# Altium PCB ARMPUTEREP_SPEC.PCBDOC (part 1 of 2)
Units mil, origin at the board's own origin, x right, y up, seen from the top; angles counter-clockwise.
Board outline 6000 x 4000 mil, 2 copper layers (Top Layer, Bottom Layer); 67 components, 140 nets, 541 pads, 398 vias.
Unrouted connection lines stored in the file: 6.
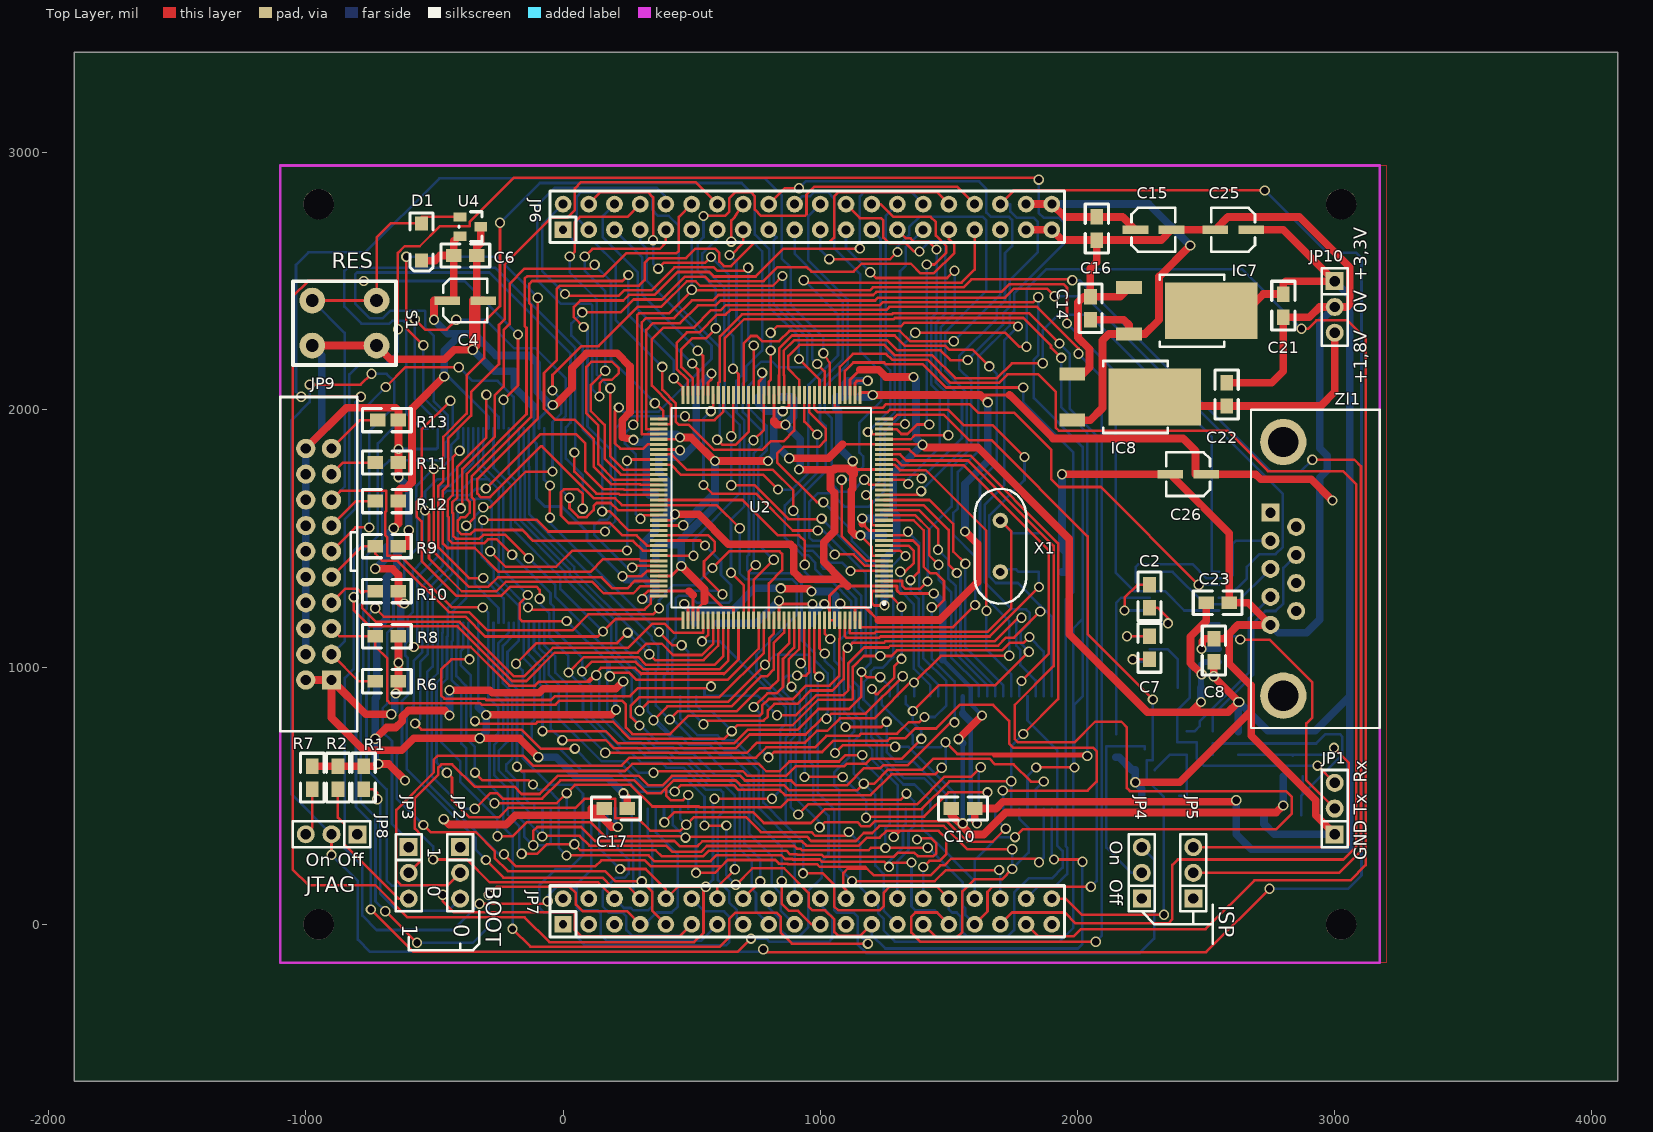
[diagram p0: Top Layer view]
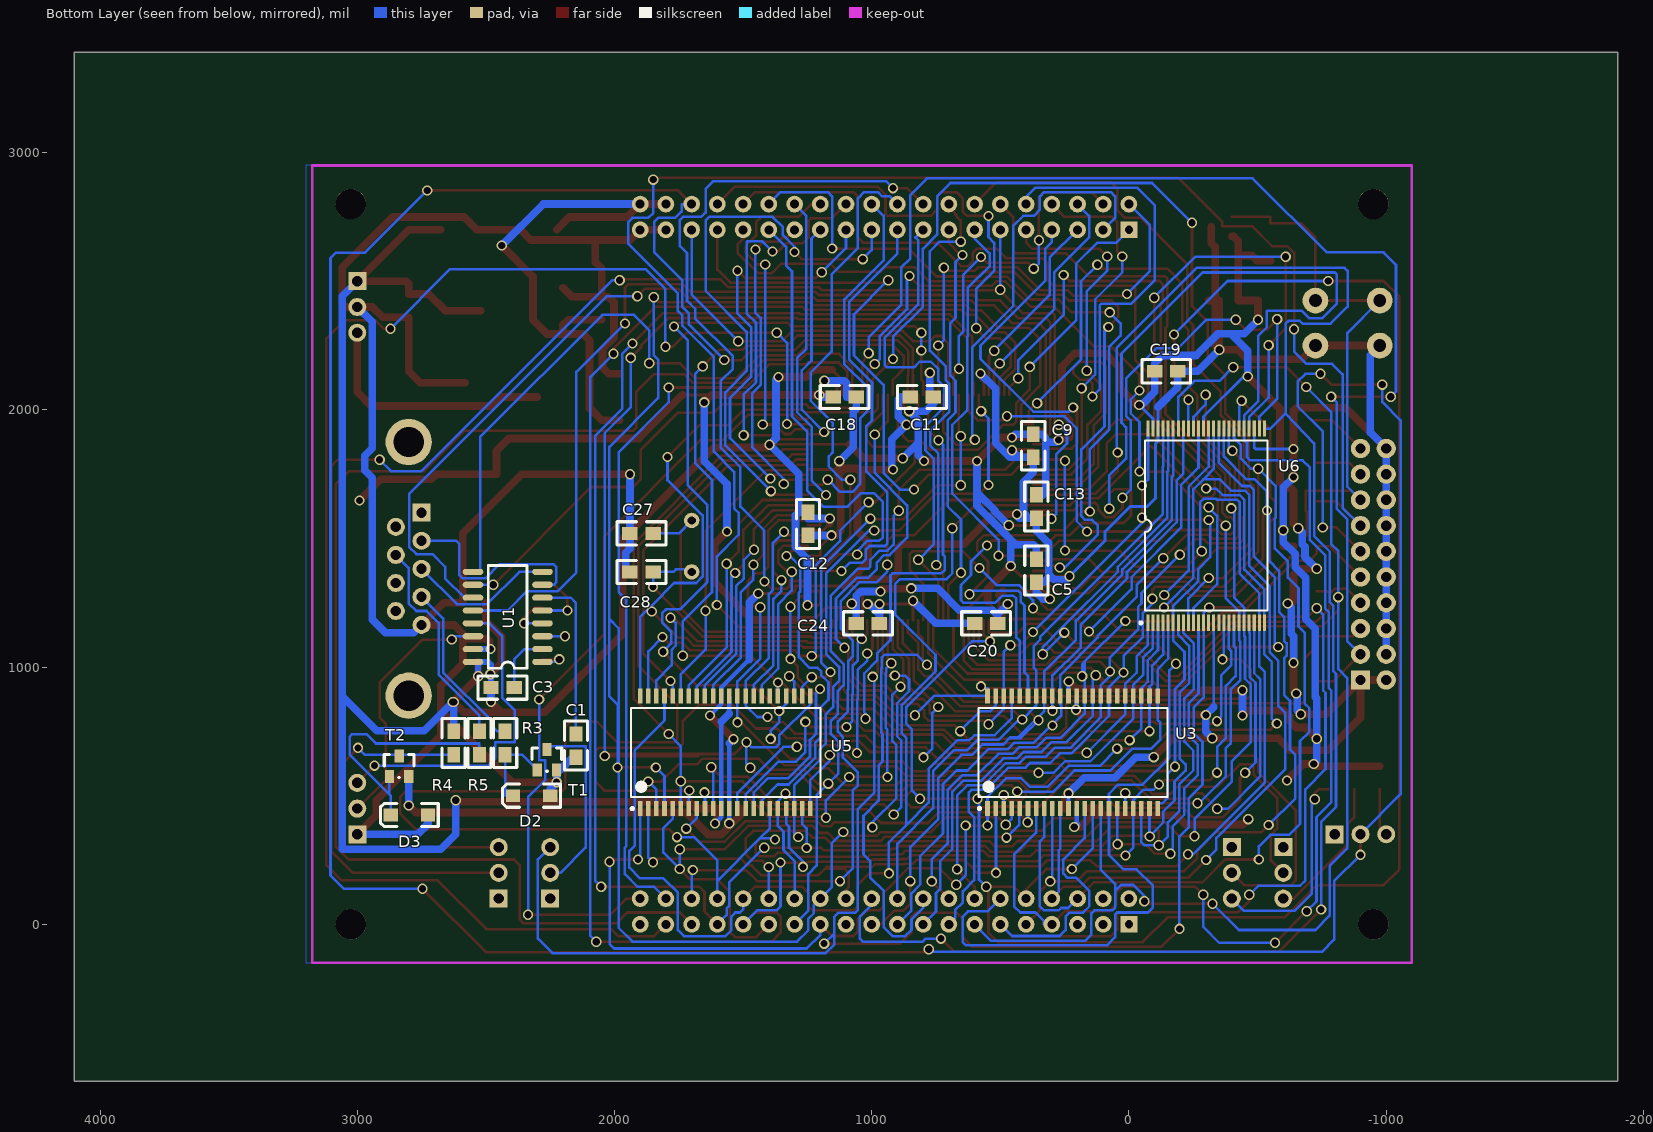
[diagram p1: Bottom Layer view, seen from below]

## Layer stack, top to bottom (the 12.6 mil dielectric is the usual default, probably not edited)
Top Layer: signal copper 1.4
Dielectric: dielectric 12.6, FR-4, Dk 4.8
Bottom Layer: signal copper 1.4

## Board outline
-1900,-610 4100,-610 4100,3390 -1900,3390

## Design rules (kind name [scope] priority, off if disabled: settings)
Clearance Clearance_1 [InComponent('U2') or InComponent('U6')] p1 off: gap=8
Clearance [All] p2: gap=15
ComponentClearance [All] p1: gap=10 collisioncheckmode=3
PolygonConnect [All] p1: connectstyle=Relief reliefconductorwidth=20 reliefentries=4 polygonreliefangle="90 Angle"
RoutingLayers [All] p1: top layer="Not Used" bottom layer="Not Used"
RoutingVias [All] p1: holewidth=28 width=40 viastyle="Through Hole" minholewidth=28 minwidth=40 maxholewidth=28 maxwidth=50
SMDNeckDown [All] p1: percent=95.000
SolderMaskExpansion [All] p1: expansion=4
TestPointUsage [All] p1: valid=0 allowmultiple=FALSE
Testpoint [All] p1: side=15 testpointundercomponent=TRUE minsize=40 maxsize=100 preferedsize=60 minholesize=0 maxholesize=40 preferedholesize=32 testpointgrid=1 style=1023 order=1234567890
Width Width_1 [InNet('+1,8V') Or InNet('+3,3V') Or InNet('+5V') Or InNet('GND')] p1: maxlimit=35 minlimit=30 preferedwidth=30
Width [All] p2: maxlimit=12 minlimit=10 preferedwidth=10
16 further rules are at their usual default settings.

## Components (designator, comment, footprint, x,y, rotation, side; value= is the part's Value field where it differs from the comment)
C1 "1u" 0805#1 2150,650 r90 bottom
C2 "1u" 0805#1 2280,1320 r270 top
C3 "1u" 0805#1 2480,920 r180 bottom
C4 "10uF" CE1SMD4X5.4 -450,2425 r0 top
C5 "100nF" 0805#1 360,1420 r270 bottom
C6 "100n" 0805#1 -425,2600 r0 top
C7 "1u" 0805#1 2280,1120 r270 top
C8 "100nF" 0805#1 2530,1020 r90 top
C9 "100nF" 0805#1 372.01,1905.43 r270 bottom
C10 "100nF" 0805#1 1600,450 r180 top
C11 "100nF" 0805#1 850,2050 r180 bottom
C12 "100nF" 0805#1 1247.99,1511.73 r90 bottom
C13 "100nF" 0805#1 360,1669.21 r270 bottom
C14 "100nF" 0805#1 2050,2350 r90 top
C15 "10uF" CE1SMD4X5.4 2225,2700 r0 top
C16 "100nF" 0805#1 2075,2750 r270 top
C17 "100nF" 0805#1 250,450 r180 top
C18 "100nF" 0805#1 1150,2050 r180 bottom
C19 "100nF" 0805#1 -100,2150 r180 bottom
C20 "100nF" 0805#1 510,1170 r0 bottom
C21 "100nF" 0805#1 2800,2450 r270 top
C22 "100nF" 0805#1 2580,2015 r90 top
C23 "100nF" 0805#1 2500,1250 r0 top
C24 "100nF" 0805#1 1060,1170 r180 bottom
C25 "10uF" CE1SMD4X5.4 2675,2700 r180 top
C26 "10uF" CE1SMD4X5.4 2500,1750 r180 top
C27 "100nF" 0805#1 1850,1520 r0 bottom
C28 "100nF" 0805#1 1850,1370 r0 bottom
D1 "1N4148" MELF2-X -550,2725 r270 top
D2 "1N4148" MELF2-X 2250,500 r0 bottom
D3 "1N4148" MELF2-X 2725,425 r0 bottom
IC7 "SPX1117-33" TO252_mod 2200,2475 r270 top
IC8 "SPX1117-18" TO252_mod 1980,2140 r270 top
JP1 "HEADER 3" sip-3 3000,350 r90 top
JP2 "BOOT0" sip-3 -400,300 r270 top
JP3 "BOOT1" sip-3 -600,300 r270 top
JP4 "JP" sip-3 2250,100 r90 top
JP5 "JP" sip-3 2450,100 r90 top
JP6 "HEADER 20X2" idc-40_65mil 0,2700 r0 top
JP7 "HEADER 20X2" idc-40_65mil 0,0 r0 top
JP8 "JP" sip-3 -800,350 r180 top
JP9 "ZWS20" IDC-20O -900,850 r90 top
JP10 "HEADER 3" sip-3 3000,2500 r270 top
R1 "10k" 0805#1 -775,525 r90 top
R2 "10k" 0805#1 -875,525 r90 top
R3 "33k" 0805#1 2425,750 r270 bottom
R4 "22k" 0805#1 2625,750 r270 bottom
R5 "33k" 0805#1 2525,750 r270 bottom
R6 "" 0805#1 -640,945 r180 top
R7 "" 0805#1 -975,525 r90 top
R8 "" 0805#1 -640,1120 r180 top
R9 "" 0805#1 -730,1470 r0 top
R10 "" 0805#1 -640,1295 r180 top
R11 "" 0805#1 -730,1795 r0 top
R12 "4x10k" 0805#1 -640,1645 r180 top
R13 "4x10k" 0805#2 -730,1960 r0 top
S1 "RESET" U_SW -975,2250 r90 top
T1 "BC850" SOT-23 2300,600 r180 bottom
T2 "BC850" SOT-23 2875,575 r180 bottom
U1 "MAX3232" SO16 2280,1020 r90 bottom
U2 "LPC2294" F-QFP20x20-G144/Z24N 810,1620 r180 top
U3 "K6R4016V1D" tsop2-44 550,450 r180 bottom
U4 "DS1818" SOT-23 -400,2750 r270 top
U5 "K6R4016V1D" tsop2-44 1900,450 r180 bottom
U6 "M29W320DB" TSOP48 -300,1550 r180 bottom
X1 "CRYSTAL" xtal 1700,1470 r90 top
Zl1 "COM0" DB-9RA/F 2750,1600 r270 top

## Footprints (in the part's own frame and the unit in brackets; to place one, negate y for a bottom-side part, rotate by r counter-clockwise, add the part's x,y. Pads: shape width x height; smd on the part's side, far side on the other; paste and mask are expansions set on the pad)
0805#1 [mil]
  rect 60x50 smd: 1(0,0) 2(90,0)
  silkscreen extent -50,-45 140,45
0805#2 [mil]
  rect 60x50 smd: 1(10,0) 2(90,0)
  silkscreen extent -50,-45 140,45
CE1SMD4X5.4 [mil]
  rect 100x33 smd: 1(0,0) 2(140,0)
  silkscreen extent -15,-85 155,85
DB-9RA/F [mil]
  rect 70x70 hole 40: 1(0,0)
  round 70 hole 40: 2(109,0) 3(218,0) 4(327,0) 5(436,0) 6(55,100) 7(164,100) 8(273,100) 9(382,100)
  round 180 hole 118: ""(-275,50) ""(711,50)
  silkscreen extent -400,-75 836,425
F-QFP20x20-G144/Z24N [mm] "QFP; 144 Leads; Body 20 x 20 mm; Pitch 0.5 mm"
  rect 1.75x0.3 smd: 1(-11.125,8.75) 2(-11.125,8.25) 3(-11.125,7.75) 4(-11.125,7.25) 5(-11.125,6.75) 6(-11.125,6.25) 7(-11.125,5.75) 8(-11.125,5.25) 9(-11.125,4.75) 10(-11.125,4.25) 11(-11.125,3.75) 12(-11.125,3.25) 13(-11.125,2.75) 14(-11.125,2.25) 15(-11.125,1.75) 16(-11.125,1.25) 17(-11.125,0.75) 18(-11.125,0.25) 19(-11.125,-0.25) 20(-11.125,-0.75) 21(-11.125,-1.25) 22(-11.125,-1.75) 23(-11.125,-2.25) 24(-11.125,-2.75) 25(-11.125,-3.25) 26(-11.125,-3.75) 27(-11.125,-4.25) 28(-11.125,-4.75) 29(-11.125,-5.25) 30(-11.125,-5.75) 31(-11.125,-6.25) 32(-11.125,-6.75) 33(-11.125,-7.25) 34(-11.125,-7.75) 35(-11.125,-8.25) 36(-11.125,-8.75) 73(11.125,-8.75) 74(11.125,-8.25) 75(11.125,-7.75) 76(11.125,-7.25) 77(11.125,-6.75) 78(11.125,-6.25) 79(11.125,-5.75) 80(11.125,-5.25) 81(11.125,-4.75) 82(11.125,-4.25) 83(11.125,-3.75) 84(11.125,-3.25) 85(11.125,-2.75) 86(11.125,-2.25) 87(11.125,-1.75) 88(11.125,-1.25) 89(11.125,-0.75) 90(11.125,-0.25) 91(11.125,0.25) 92(11.125,0.75) 93(11.125,1.25) 94(11.125,1.75) 95(11.125,2.25) 96(11.125,2.75) 97(11.125,3.25) 98(11.125,3.75) 99(11.125,4.25) 100(11.125,4.75) 101(11.125,5.25) 102(11.125,5.75) 103(11.125,6.25) 104(11.125,6.75) 105(11.125,7.25) 106(11.125,7.75) 107(11.125,8.25) 108(11.125,8.75)
  rect 0.3x1.75 smd: 37(-8.75,-11.125) 38(-8.25,-11.125) 39(-7.75,-11.125) 40(-7.25,-11.125) 41(-6.75,-11.125) 42(-6.25,-11.125) 43(-5.75,-11.125) 44(-5.25,-11.125) 45(-4.75,-11.125) 46(-4.25,-11.125) 47(-3.75,-11.125) 48(-3.25,-11.125) 49(-2.75,-11.125) 50(-2.25,-11.125) 51(-1.75,-11.125) 52(-1.25,-11.125) 53(-0.75,-11.125) 54(-0.25,-11.125) 55(0.25,-11.125) 56(0.75,-11.125) 57(1.25,-11.125) 58(1.75,-11.125) 59(2.25,-11.125) 60(2.75,-11.125) 61(3.25,-11.125) 62(3.75,-11.125) 63(4.25,-11.125) 64(4.75,-11.125) 65(5.25,-11.125) 66(5.75,-11.125) 67(6.25,-11.125) 68(6.75,-11.125) 69(7.25,-11.125) 70(7.75,-11.125) 71(8.25,-11.125) 72(8.75,-11.125) 109(8.75,11.125) 110(8.25,11.125) 111(7.75,11.125) 112(7.25,11.125) 113(6.75,11.125) 114(6.25,11.125) 115(5.75,11.125) 116(5.25,11.125) 117(4.75,11.125) 118(4.25,11.125) 119(3.75,11.125) 120(3.25,11.125) 121(2.75,11.125) 122(2.25,11.125) 123(1.75,11.125) 124(1.25,11.125) 125(0.75,11.125) 126(0.25,11.125) 127(-0.25,11.125) 128(-0.75,11.125) 129(-1.25,11.125) 130(-1.75,11.125) 131(-2.25,11.125) 132(-2.75,11.125) 133(-3.25,11.125) 134(-3.75,11.125) 135(-4.25,11.125) 136(-4.75,11.125) 137(-5.25,11.125) 138(-5.75,11.125) 139(-6.25,11.125) 140(-6.75,11.125) 141(-7.25,11.125) 142(-7.75,11.125) 143(-8.25,11.125) 144(-8.75,11.125)
  silkscreen extent -11.25,-9.85 9.85,9.85
IDC-20O [mil]
  rect 75x75 hole 40: 1(100,0)
  round 75 hole 40: 2(100,100) 3(200,0) 4(200,100) 5(300,0) 6(300,100) 7(400,0) 8(400,100) 9(500,0) 10(500,100) 11(600,0) 12(600,100) 13(700,0) 14(700,100) 15(800,0) 16(800,100) 17(900,0) 18(900,100) 19(1000,0) 20(1000,100)
  silkscreen extent -100,-100 1200,200
idc-40_65mil [mil]
  rect 65x65 hole 32: 1(0,0)
  round 65 hole 35: 2(0,100) 3(100,0) 4(100,100) 5(200,0) 6(200,100) 7(300,0) 8(300,100) 9(400,0) 10(400,100) 11(500,0) 12(500,100) 13(600,0) 14(600,100) 15(700,0) 16(700,100) 17(800,0) 18(800,100) 19(900,0) 20(900,100) 21(1000,0) 22(1000,100) 23(1100,0) 24(1100,100) 25(1200,0) 26(1200,100) 27(1300,0) 28(1300,100) 29(1400,0) 30(1400,100) 31(1500,0) 32(1500,100) 33(1600,0) 34(1600,100) 35(1700,0) 36(1700,100) 37(1800,0) 38(1800,100) 39(1900,0) 40(1900,100)
  silkscreen extent -50,-50 1950,150
MELF2-X [mil]
  rect 55x50 smd: 1(0,0) 2(145,0)
  silkscreen extent -40,-45 185,45
sip-3 [mil]
  rect 70x70 hole 40: 1(0,0)
  round 70 hole 40: 2(100,0) 3(200,0)
  silkscreen extent -50,-50 250,50
SO16 [mil]
  oval 24x80 smd: 1(0,0) 2(50,0) 3(100,0) 4(150,0) 5(200,0) 6(250,0) 7(300,0) 8(350,0) 9(350,270) 10(300,270) 11(250,270) 12(200,270) 13(150,270) 14(100,270) 15(50,270) 16(0,270)
  silkscreen extent -25,60 375,210
SOT-23 [mil]
  rect 36x50 smd: 1(0,0) 2(75,0) 3(38,80)
  silkscreen extent -20,-5 95,85
TO252_mod [mil]
  rect 50x100 smd: 1(0,0) 3(180,0)
  rect 220x360 smd: 2(90,320)
  silkscreen extent -50,120 230,370
tsop2-44 [mm]
  rect 0.45x1.5 smd: 1(0,0) 2(0.8,0) 3(1.6,0) 4(2.4,0) 5(3.2,0) 6(4,0) 7(4.8,0) 8(5.6,0) 9(6.4,0) 10(7.2,0) 11(8,0) 12(8.8,0) 13(9.6,0) 14(10.4,0) 15(11.2,0) 16(12,0) 17(12.8,0) 18(13.6,0) 19(14.4,0) 20(15.2,0) 21(16,0) 22(16.8,0) 23(16.8,11.1) 24(16,11.1) 25(15.2,11.1) 26(14.4,11.1) 27(13.6,11.1) 28(12.8,11.1) 29(12,11.1) 30(11.2,11.1) 31(10.4,11.1) 32(9.6,11.1) 33(8.8,11.1) 34(8,11.1) 35(7.2,11.1) 36(6.387,11.113) 37(5.6,11.1) 38(4.8,11.1) 39(4,11.1) 40(3.2,11.1) 41(2.4,11.1) 42(1.6,11.1) 43(0.8,11.1) 44(0,11.1)
  silkscreen extent -0.91,-0.12 17.78,9.95
TSOP48 [mm] "Shrink Small Outline, Plastic, Thin; 48 Leads; Body Width 18.4 mm; Pitch 0.5 mm"
  rect 0.3x1.6 smd: 1(-5.75,-9.6) 2(-5.25,-9.6) 3(-4.75,-9.6) 4(-4.25,-9.6) 5(-3.75,-9.6) 6(-3.25,-9.6) 7(-2.75,-9.6) 8(-2.25,-9.6) 9(-1.75,-9.6) 10(-1.25,-9.6) 11(-0.75,-9.6) 12(-0.25,-9.6) 13(0.25,-9.6) 14(0.75,-9.6) 15(1.25,-9.6) 16(1.75,-9.6) 17(2.25,-9.6) 18(2.75,-9.6) 19(3.25,-9.6) 20(3.75,-9.6) 21(4.25,-9.6) 22(4.75,-9.6) 23(5.25,-9.6) 24(5.75,-9.6) 25(5.75,9.6) 26(5.25,9.6) 27(4.75,9.6) 28(4.25,9.6) 29(3.75,9.6) 30(3.25,9.6) 31(2.75,9.6) 32(2.25,9.6) 33(1.75,9.6) 34(1.25,9.6) 35(0.75,9.6) 36(0.25,9.6) 37(-0.25,9.6) 38(-0.75,9.6) 39(-1.25,9.6) 40(-1.75,9.6) 41(-2.25,9.6) 42(-2.75,9.6) 43(-3.25,9.6) 44(-3.75,9.6) 45(-4.25,9.6) 46(-4.75,9.6) 47(-5.25,9.6) 48(-5.75,9.6)
  silkscreen extent -6.57,-9.72 6.05,8.4
U_SW [mil]
  round 100 hole 50: 1(175,0) 1(175,-250) 2(0,0) 2(0,-250)
  silkscreen extent -75,-325 250,75
xtal [mil]
  round 60 hole 32: 1(-100,0) 2(100,0)
  silkscreen extent -224,-100 224,100

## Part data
C1 C2 C3 C5 C6 C7 C8 C9 C10 C11 C12 C13 C14 C16 C17 C18 C19 C20 C21 C22 C23 C24 C27 C28: library part CAP, "Capacitor"
C4 C15 C25 C26: library part CP, "Capacitor"
D1 D2 D3: library part DIODE, "Diode"
IC7 IC8: library part STAB2
JP2 JP3: library part JP, "Jumper"
JP4 JP5 JP8: "Jumper"
JP9: library part "HEADER 10X2"
R1 R2: library part RES2
R3 R4 R5 R6 R7 R8 R9 R10 R11 R12 R13: library part REZY1
S1: library part SW-PB
T1 T2: library part NPN1, "NPN Transistor"
U1: library part MAX232
U2: library part LPC2292
U3 U5: library part IDT71V416S
U4: library part DS1813
X1: "Crystal"
Zl1: library part DB9

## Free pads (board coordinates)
  round 118.11 hole 118.11: 0(-950,2800) 1(-950,0) 2(3025,2800) 3(3025,0)

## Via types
v1: diameter 40, hole 28, Top Layer to Bottom Layer, 398 vias

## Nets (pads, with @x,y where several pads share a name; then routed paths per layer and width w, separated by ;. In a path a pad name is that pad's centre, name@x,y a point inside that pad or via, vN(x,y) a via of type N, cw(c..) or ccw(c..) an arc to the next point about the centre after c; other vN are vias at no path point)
+1,8V: C18.1 C20.1 C22.1 C24.1 C26.1 IC8.2 JP10.3 U2.37 U2.110 U2.143 | length 5459.7
  Top Layer w11.22: v1(471,1245) 485.2,1230.8 U2.110@485.2,1182.01 ; v1(1078,1246) 1093,1231 1134.8,1231 ; U2.143@1134.8,1182.01 1134.8,1231 ; U2.37@1154.49,2057.99 1154.49,2067.61 1194.39,2067.61 v1(1204,2058) ; 1225,1183 1177,1231 1134.8,1231 ; 1622,2058 1736,2058
  Top Layer w30: v1(846,1306) 848,1304 956,1304 v1(966,1294) ; v1(1204,2058) 1622,2058 v1(1651,2029) ; 1225,1183 1464.6,1183 1611,1329.4 1611,1479 v1(1563,1527) ; 1736,2058 1905,1889 2410,1889 2459,1840 2459,1750 C26.1@2500,1750 2691.91,1750 2712,1729.91 2908.59,1729.91 v1(2991,1647.5) ; IC8.2@2300,2050 2439,2050 2474,2015 C22.1@2580,2015 2945,2015 3000,2070 JP10.3@3000,2300
  Bottom Layer w30: v1(471,1245) 512.5,1203.5 ; C20.1@510,1170 510,1201 512.5,1203.5 ; v1(846,1306) 744,1306 659,1221 530,1221 512.5,1203.5 ; v1(966,1294) 1043.15,1294 1060,1277.15 1060,1246 1060,1228 ; C24.1@1060,1170 1060,1228 ; v1(1078,1246) 1060,1228 ; C18.1@1150,2050 1196,2050 v1(1204,2058) ; v1(1563,1527) 1563,1712 1651,1800 v1(1651,2029)
+3,3V: C3.1 C4.1 C5.1 C6.1 C8.1 C9.1 C10.1 C11.2 C12.2 C13.1 C17.1 C19.1 C21.1 C23.1 C25.1 D1.2 IC7.2 JP9.1 JP9.2 JP10.1 R4.1 R6.1 R8.1 R10.1 R12.1 U1.16 U2.2 U2.14 U2.31 U2.39 U2.51 U2.57 U2.77 U2.94 U2.104 U2.112 U2.119 U3.11 U3.33 U4.2 U5.11 U5.33 U6.14 U6.37 U6.47 | length 21572.6
  Top Layer w11.22: U2.104@372.01,1354.25 420.82,1354.25 v1(459.57,1393) 550,1302.57 621.57,1231 662.36,1231 U2.119@662.36,1182.01 ; U2.94@372.01,1551.1 v1@466.9,1551.1 ; U2.77@372.01,1885.75 455,1885.75 504.25,1885.75 ; U2.112@524.57,1182.01 524.57,1230 550,1255.43 ; U2.57@760.79,2057.99 760.79,2109 774,2122.21 v1(774,2144) ; v1(854,1995) 869,2010 878.9,2010 U2.51@878.9,2057.99 ; 1086.25,1866.06 U2.31@1247.99,1866.06 v1@1394.94,1866.06 ; U2.39@1115.12,2057.99 1115.12,2117.12 1154,2156 ; v1@1163.42,1558 1190,1531.42 U2.14@1247.99,1531.42 ; U2.2@1247.99,1295.2 1199,1295.2 1199,1250 1209,1240 v1(1250,1240)
  Top Layer w30: JP9.2@-1000,950 JP9.1@-900,950 ; v1(-730,1382) -663.24,1382 -640,1358.76 R10.1@-640,1295 -640,1257 -630,1247 v1(-617,1247) ; v1(-668,817) -767,817 JP9.1@-900,950 ; v1(-658,1540) -640,1558 R12.1@-640,1645 -640,1685 -630,1695 -610,1695 -587,1718 -587,2005 v1(-462,2130) ; v1(-650,897) -640,907 R6.1@-640,945 v1(-640,1017) R8.1@-640,1120 ; D1.2@-550,2580 -498,2580 -478,2600 C6.1@-425,2600 ; v1(-502,2350) -502,2425 C4.1@-450,2425 -425,2425 C6.1@-425,2600 ; U4.2@-400,2675 -406,2675 -425,2656 C6.1@-425,2600 ; v1(-299,814) -298.25,814.75 186.75,814.75 v1(206,834) ; v1(-96.08,650) -169.68,723.6 v1(-324,723.6) -580.4,723.6 -627,677 -774,677 -900,803 JP9.1@-900,950 ; v1(-40,2019) -30,2019 34.49,2083.49 34.49,2162.49 91.56,2219.56 210,2219.56 260,2169.56 260,1990.02 230,1960.02 230,1894.02 v1(274,1883.36) ; v1(235.04,509) 250,494.04 C17.1@250,450 ; v1(455,1892.69) 497.31,1892.69 504.25,1885.75 589,1801 v1(591,1801) v1(797,1801) ; v1(459.57,1393) 550,1302.57 550,1255.43 ; v1@466.9,1551.1 v1(467,1551) ; v1(879,1811.81) 1032,1811.81 1086.25,1866.06 ; 1154,2156 1227,2156 1255,2128 v1(1362,2128) ; v1@1163.42,1558 v1(1163.42,1577.73) ; v1@1394.94,1866.06 v1(1397,1864) 1407,1854 1612,1854 1968,1498 1968,1128 2272,824 2440,824 ; v1(1609,392) 1600,401 C10.1@1600,450 1683,450 1710,477 2612,477 v1(2617,482) ; v1(2480,864) 2440,824 ; v1(2482.5,972.5) 2439,1016 2439,1118 2500,1179 C23.1@2500,1250 ; IC7.2@2520,2385 2657,2385 2722,2450 C21.1@2800,2450 2800,2490 2810,2500 JP10.1@3000,2500 2800,2700 C25.1@2675,2700 ; v1(2530,963) 2627,866 v1(2629,864) ; v1(2530,965) C8.1@2530,1020 ; v1(2625,864) 2585,824 2440,824
  Bottom Layer w11.22: v1@-462,2145.84 -454.08,2137.92 -290.16,1974 U6.37@-290.16,1927.95 ; -329.53,844.53 U6.14@-329.53,1172.05 ; U6.47@-93.31,1927.95 -93.31,1965.69 v1(-40,2019)
  Bottom Layer w16.83: U3.33@203.54,887.01 203.54,836.46 v1(206,834) ; U3.11@235.04,450 v1(235.04,509) ; 1553.54,819.25 U5.33@1553.54,887.01 ; 1585.04,787.76 U5.11@1585.04,450 1585.04,415.96 v1(1609,392)
  Bottom Layer w22.8: C3.1@2480,920 2480,972.5 2480,1010 2490,1020 2492.5,1020 ; v1(2482.5,972.5) 2482.5,1010 2492.5,1020 ; v1(2530,963) v1(2530,965) U1.16@2530,1020 ; U1.16@2550,1020 U1.16@2530,1020 ; 2492.5,1020 U1.16@2530,1020
  Bottom Layer w30: v1(-730,1382) -684,1428 -684,1467.98 -674,1477.98 -674,1524 v1(-658,1540) ; v1(-668,817) -654,831 -654,893 v1(-650,897) ; v1(-640,1017) -641,1018 -641,1120 -631,1130 -631,1233 v1(-617,1247) ; v1(-502,2350) -448,2296 -396,2296 ; v1(-462,2130) -462,2145.84 -462,2230 -396,2296 ; -329.53,844.53 v1(-299,814) -299,748.6 v1(-324,723.6) ; v1(-96.08,650) -25.86,650 54.14,570 174.04,570 v1(235.04,509) ; v1(-40,2019) -49,2019 -100,2070 C19.1@-100,2150 -100,2180.58 -130.92,2211.5 -261.79,2211.5 -346.29,2296 -396,2296 ; v1(274,1883.36) 283.35,1874.02 324,1874.02 ; C5.1@360,1420 360,1466 370,1476 440.13,1476 459.57,1495.44 ; C13.1@360,1669.21 334.79,1669.21 324,1680 324,1874.02 ; v1(455,1892.69) 442.26,1905.43 C9.1@372.01,1905.43 339.43,1905.43 324,1890 324,1874.02 ; v1(459.57,1393) 459.57,1495.44 ; v1(467,1551) 496.42,1580.42 520.49,1604.49 520.49,1608.06 591,1678.57 ; v1(591,1801) 591,1678.57 ; v1(774,2144) 774,2061.97 762.03,2050 C11.2@760,2050 760,2024.46 789.46,1995 v1(854,1995) 819,1960 819,1871.81 ; v1(797,1801) 819,1823 819,1871.81 ; v1(879,1811.81) 819,1871.81 ; v1(1163.42,1577.73) 1247.99,1577.73 C12.2@1247.99,1601.73 1284,1601.73 ; v1(1250,1240) 1250,1421 1296,1467 1296,1590 1284.27,1601.73 1284,1601.73 ; v1(1362,2128) 1372,2118 1372,1889 v1(1397,1864) 1284,1751 1284,1601.73 ; 1553.54,819.25 1585.04,787.76 ; v1(2480,864) C3.1@2480,920 ; v1(2617,482) 2617,350 2675,292 3058,292 3058,887 ; R4.1@2625,750 v1(2625,864) ; v1(2629,864) 2740,753 2924,753 3058,887 ; JP10.1@3000,2500 3058,2442 3058,887 ; 459.57,1495.44 491.07,1526.93 520.49,1556.36 591,1626.87 591,1678.57
+5V: C14.1 C15.1 C16.1 IC7.3 IC8.3 JP6.38 JP6.40 | length 2256.1
  Top Layer w30: JP6.38@1800,2800 JP6.40@1900,2800 1950,2750 C16.1@2075,2750 2175,2750 C15.1@2225,2700 ; IC8.3@1980,1960 2050,1960 2097,2007 2097,2270 2122,2295 IC7.3@2200,2295 ; C14.1@2050,2350 2180,2350 2200,2330 IC7.3@2200,2295 ; v1(2438,2639) 2317,2518 2317,2350 2262,2295 IC7.3@2200,2295
  Bottom Layer w30: JP6.40@1900,2800 2277,2800 v1(2438,2639)
/BLS0: U2.96 U3.39 | length 1099.4
  Top Layer w10: U2.96@372.01,1511.73 565.27,1511.73 590,1487 590,1453 548,1411 548,1355 v1(620,1283)
  Bottom Layer w10: U3.39@392.52,887.01 392.52,965.48 406,978.96 406,1239 420,1253 420,1286 430,1296 607,1296 v1(620,1283)
/BLS1: U2.97 U3.40 | length 1063.2
  Top Layer w10: U2.97@372.01,1492.05 532.95,1492.05 v1(552,1473)
  Bottom Layer w10: U3.40@424.02,887.01 424.02,1101.02 438,1115 438,1266 450,1278 492,1278 520,1250 643,1250 653,1260 653,1319 614,1358 614,1411 v1(552,1473)
/BLS2: U2.27 U5.39 | length 1187.6
  Top Layer w10: U2.27@1247.99,1787.32 1288.68,1787.32 1310,1766 1410,1766 1646,1530 v1(1646,1219)
  Bottom Layer w10: v1(1646,1219) 1646,1067.52 1742.52,971 U5.39@1742.52,887.01
/BLS3: U2.28 U5.40 | length 1401.3
  Top Layer w10: U2.28@1247.99,1807.01 1294.45,1807.01 1316.46,1785 1557,1785 1889,1453 1889,1052.98 v1(1782.02,946)
  Bottom Layer w10: U5.40@1774.02,887.01 1774.02,938 v1(1782.02,946)
/CS0: U2.91 U6.26 | length 2096.4
  Top Layer w10: v1(-576,2352) -536,2312 -453,2312 v1(-415,2350) ; v1(25,1658) 25,1618 60,1583 92,1583 119,1610 119,1627 130,1638 185,1638 212.84,1610.16 U2.91@372.01,1610.16
  Bottom Layer w10: v1(-576,2352) -576,2043 -506.69,1973.69 U6.26@-506.69,1927.95 ; v1(-415,2350) -300.39,2350 -189.89,2239.5 -107.5,2239.5 11,2121 11,1977 -7,1959 -7,1690 v1(25,1658)
/CS1: U2.30 U3.6 U5.6 | length 3437.4
  Top Layer w10: v1(394,397) 433,436 739,436 781,394 964,394 1018,448 1394,448 1502,556 v1(1742.52,556) ; U2.30@1247.99,1846.38 1345.62,1846.38 1370,1822 1583.4,1822 1925,1480.4 1925,876 v1(1789,740)
  Bottom Layer w10: U3.6@392.52,450 392.52,398.48 v1(394,397) ; U5.6@1742.52,450 v1(1742.52,556) 1742.52,693.52 v1(1789,740)
/CS2: JP7.37 U2.35 | length 6122.9
  Top Layer w10: U2.35@1247.99,1944.8 1328.8,1944.8 v1(1329,1945) ; v1(1369,2300) 1719,2300 1774,2245 v1(1802,2245) ; JP7.37@1800,0 1846,-46 1986,-46 2013,-19 2498,-19 2688,171 3061,171 3120,230 3120,2278 3050,2348 2929,2348 2896,2315 v1(2871,2315)
  Bottom Layer w10: v1(1329,1945) 1329,2260 v1(1369,2300) ; v1(1802,2245) 1802,2469 1880,2547 2639,2547 v1(2871,2315)
/CS3: JP7.40 U2.36 | length 3084.5
  Top Layer w10: U2.36@1247.99,1964.49 1282.49,1964.49 1299.5,1981.5 1479.49,1981.5 1578.99,1882 1665.43,1882 2039,1508.43 2039,1128 v1(2293,874) ; JP7.40@1900,100 1954,100 2017,37 v1(2336,37)
  Bottom Layer w10: v1(2293,874) 2293,638 2269,638 2269,562 2336,495 v1(2336,37)
/OE: JP7.32 U2.90 U3.41 U5.41 U6.28 | length 8079
  Top Layer w10: v1(-609,2595) -609,2317 v1(-543,2251) ; v1(-98,2436) -98,1967 -333,1732 -333,1674 -320,1661 -284,1661 -87,1858 -81,1858 121,1656 203,1656 229.16,1629.84 U2.90@372.01,1629.84 597.16,1629.84 v1(687,1540) ; v1(933,198) 1010,198 1054,154 1054,70 1070,54 1230,54 1246,70 1246,122 1270,146 1454,146 JP7.32@1500,100
  Bottom Layer w10: v1(-609,2595) -257,2595 v1(-98,2436) ; v1(-543,2251) -543,2047 -467.32,1971.32 U6.28@-467.32,1927.95 ; U3.41@455.51,887.01 455.51,801.49 522,735 601,735 621,715 667.68,715 779,603.68 779,473 865,387 ; v1(687,1540) 687,1364 709,1342 890,1342 909,1323 909,1205 752,1048 752,983.54 883,852.54 883,742 865,724 865,387 ; v1(933,198) 933,319 865,387 ; JP7.32@1500,100 1500,58 1512,46 1530,46 1546,30 1546,-23 1569,-46 1730,-46 1754,-22 1754,123 1810,179 1901,179 1942,220 1942,285 1922,305 1922,676.51 1805.51,793 U5.41@1805.51,887.01
/WE: JP7.34 U2.29 U3.17 U5.17 U6.11 | length 7861.6
  Top Layer w10: v1(-161,274) -101,274 -64,311 v1(44,311) 67,288 360,288 384,264 544.42,264 567,286.58 868.42,286.58 883,272 909,272 911,270 1006,270 1014,262 1285,262 1301,278 1366,278 1379,265 1440,265 1451,276 1451,314 1430,335 1381,335 v1(1376,330) ; U2.29@1247.99,1826.69 1310.31,1826.69 1334,1803 1575,1803 1907,1471 1907,1004 1756,853 1756,720 1769,707 1988,707 2069,788 2170,788 2192,766 2192,530 2204,518 2810,518 2833,495 2833,430 2773,370 1788,370 v1(1757,339)
  Bottom Layer w10: U6.11@-270.47,1172.05 -270.47,898.22 -233.26,861 -233.26,731.74 -268,697 -268,581 -215,528 -215,426 -171,382 -171,284 v1(-161,274) ; v1(44,311) 46.06,313.06 U3.17@46.06,450 ; v1(1376,330) 1381,335 1434.06,335 ; U5.17@1396.06,450 1396.06,373 1434.06,335 ; JP7.34@1600,100 1600,169.06 ; v1(1757,339) 1690,339 1600,249 1600,169.06 ; 1434.06,335 1600,169.06
A0: JP7.23
A1: JP7.22 U2.88 U6.25 | length 6852.3
  Top Layer w10: v1(-747,58) -582,-107 679,-107 v1(730.37,-55.63) ; v1(44,1834) 44,1759.56 129.56,1674 216.21,1674 221,1669.21 U2.88@372.01,1669.21
  Bottom Layer w10: v1(-747,58) -747,398 -805,456 -805,974 -795,984 -795,1238 -781,1252 -781,1448.43 -720,1509.43 -720,1870 -609,1986 ; U6.25@-526.38,1927.95 -526.38,1927 -550,1927 -609,1986 ; v1(44,1834) 47,1837 47,2241.63 -263.37,2552 -838,2552 -850,2540 -850,2401 -784,2335 -675,2335 -664,2346 -620,2346 -609,2335 -609,1986 ; v1(730.37,-55.63) 791.09,-55.63 803.46,-68 1034,-68 1046,-56 1046,30 1000,76 JP7.22@1000,100
A2: JP7.25 U2.87 U3.1 U5.1 U6.24 | length 5981.3
  Top Layer w10: v1(-575,781) -551,757 -161.08,757 -87.08,683 v1(46,683) ; v1(-300,1694) -89,1905 52,1905 87,1870 87,1760.91 155.91,1692 235.9,1692 239,1688.9 U2.87@372.01,1688.9 ; v1(550,384) v1(635,384) ; v1(671.5,153.5) 736,218 859,218 954.5,122.5 954.5,70 970,54.5 1018.5,54.5 1054.5,18.5 1054.5,-30 1070,-45.5 1154.5,-45.5 JP7.25@1200,0 ; v1(1909,252) 2010,252 v1(2019,243)
  Bottom Layer w10: v1(-575,781) -555,801 -555,1021 -526.38,1049.62 U6.24@-526.38,1172.05 -526.38,1301.24 -449,1378.62 -449,1650 -431,1668 -365,1668 -339,1694 v1(-300,1694) ; v1(46,683) 113,616 234.32,616 316.32,534 385,534 418.68,567.68 478.32,567.68 550,496 U3.1@550,450 v1(550,384) ; v1(635,384) 635,190 v1(671.5,153.5) ; JP7.25@1200,0 1200,-41.12 1252.88,-94 2001.4,-94 2019,-76.4 v1(2019,243) ; U5.1@1900,450 1900,261 v1(1909,252)
A3: JP7.24 U2.81 U3.2 U5.2 U6.23 | length 5924.1
  Top Layer w10: v1(-283,1450) -223,1390 -27,1390 36,1453 v1(249,1453) ; v1(-229.29,272.29) -182,225 125,225 149,249 317.97,249 342,224.97 517,224.97 614.97,224.97 ; v1(249,1802) 254.01,1807.01 U2.81@372.01,1807.01 ; v1(517,200) 590,200 614.97,224.97 ; JP7.24@1100,100 1100,134 1090,144 1090,200 1106,216 1182,216 ; v1(1850,241) 1836,255 1509.2,255 1483.2,229 1467.5,229 1428.5,190 1208,190 1182,216 ; 614.97,224.97 640,250 825.42,250 839.42,236 872.42,236 874.42,234 987,234 998,223 1175,223 1182,216
  Bottom Layer w10: v1(-283,1450) -277,1456 -277,1641 -290,1654 -339,1654 -343,1650 -421,1650 -431,1640 -431,1362.68 -506.69,1286.99 U6.23@-506.69,1172.05 -506.69,1002 -528,980.69 -528,551 -249.29,272.29 v1(-229.29,272.29) ; v1(249,1453) v1(249,1802) ; v1(517,200) 517,410 518.5,411.5 U3.2@518.5,450 ; v1(1850,241) 1868.5,259.5 U5.2@1868.5,450
A4: JP7.27 U2.80 U3.3 U5.3 U6.22 | length 6091
  Top Layer w10: v1(-343.28,449) -282.28,510 -256.28,510 -235,488.72 -81.28,488.72 -10,560 277.24,560 327.24,510 381.24,510 401,529.76 ; U2.80@372.01,1826.69 422,1826.69 481.69,1767 816,1767 895,1688 v1(895,1608) ; v1(487,502.99) 467.01,483 418,483 401,500 401,529.76 ; v1(1868.46,555) 1819,555 1752,622 1679,622 1657,644 1439.79,644 1396.79,601 1264,601 1210,547 v1(1169,547) 1144,522 878,522 859,541 690,541 672,559 430.24,559 401,529.76
  Bottom Layer w10: U6.22@-487.01,1172.05 -487.01,976 -510,953.01 -510,575 -384,449 v1(-343.28,449) ; U3.3@487.01,450 v1(487,502.99) ; v1(895,1608) 915,1588 915,1476.41 938.57,1452.84 969.38,1452.84 1005,1417.23 1005,1390 1012,1383 1054,1383 1159,1278 1159,1061 1109,1011 1109,930 1132,907 1132,817.5 1159,790.5 1159,740 1130,711 1130,586 v1(1169,547) 1214,502 1214,228 1246,196 1246,54 JP7.27@1300,0 ; U5.3@1837.01,450 1837.01,523.55 v1(1868.46,555)
A5: JP7.26 U2.74 U3.4 U5.4 U6.21 | length 9210.8
  Top Layer w10: v1(-451.62,589) -450,589 -431.62,570.62 -431.62,483.62 -364,416 -249.44,416 -213,452.44 47.57,452.44 83.13,488 203,488 203,412 291,412 339,364 456,364 v1(479,387) 509,417 711.27,417 769.69,358.58 965.83,358.58 980.42,344 1096.42,344 v1(1111,358.58) ; U2.74@372.01,1944.8 419.8,1944.8 419.8,2019.2 345,2094 345,2274.97 389.03,2319 507,2319 576,2388 613.46,2388 632.46,2407 1231.59,2407 1242.59,2418 1827,2418 v1(1847,2438) ; v1(1839.08,610) v1(1988,610)
  Bottom Layer w10: U6.21@-467.32,1172.05 -467.32,1134.93 -469,1133.26 -469,962.1 -492,939.1 -492,629.38 v1(-451.62,589) ; U3.4@455.51,450 455.51,410.49 v1(479,387) ; v1(1111,358.58) 1156,313.58 1156,144 JP7.26@1200,100 1225.08,74.92 1225.08,43 1246,22.08 1246,-23 1290,-67 1930,-67 1983.4,-13.6 1983.4,610 1983.4,1150.02 2020,1186.62 ; U5.4@1805.51,450 1805.51,576.43 v1(1839.08,610) ; v1(1847,2438) 1847,2212 1830,2195 1830,2046 2020,1856 2020,1186.62 ; v1(1988,610) 1988,854 2020,886 2020,1186.62
A6: JP7.29 U2.73 U3.5 U5.5 U6.20 | length 6617.7
  Top Layer w10: v1(-398,1617) -391.6,1623.4 -391.6,1770.49 -265,1897.09 -265,2056.89 -230.98,2090.91 -230.98,2310.51 -207.97,2333.52 -207.97,2490.03 -149,2549 108,2549 v1(122.77,2563.77) ; v1(-255,342) -196.33,342 -141.89,396.44 108.78,396.44 163.22,342 476,342 477.42,340.58 v1@479.58,340.58 ; v1(357,2026) 360,2026 390,1996 390,1964.49 U2.73@372.01,1964.49 ; v1(476,337) v1@479.58,340.58 ; JP7.29@1400,0 1450,-50 1532,-50 1552,-30 1552,128 1599,175 1706,175 v1(1746,215) ; v1(1746,292) 1571,292 1480,383 1230,383 1202,355 1169,355 1138,324 964.42,324 947.83,340.58 v1@479.58,340.58
  Bottom Layer w10: v1(-398,1617) -409,1606 -409,1270 -447.64,1231.36 U6.20@-447.64,1172.05 -447.64,1121 -451,1117.64 -451,954.64 -474,931.64 -474,708 -399,633 -399,554 -255,410 v1(-255,342) ; v1(122.77,2563.77) 186.57,2499.98 186.57,2196.43 v1(357,2026) ; U3.5@424.02,450 424.02,439 427,436.02 427,386 v1(476,337) ; v1(1746,292) v1(1746,215) 1810,279 1810,374.02 1774.02,410 U5.5@1774.02,450
A7: JP7.28 U2.72 U3.18 U5.18 U6.19 | length 5380.3
  Top Layer w10: v1(-376,1550) -345,1581 -345,1650 -355.6,1660.6 -355.6,1740.67 -124,1972.27 -124,2407 -131,2414 -131,2490 -120,2501 231,2501 v1(254,2524) ; v1(-266.72,470.72) -24.71,470.72 v1(14.57,510) 46.57,542 263,542 347,458 527,458 530,455 845,455 874,484 1311,484 v1(1335,508) ; v1(430,2122.51) 465.51,2087 U2.72@465.51,2057.99
  Bottom Layer w10: v1(-376,1550) -376,1268.95 -427.95,1217 U6.19@-427.95,1172.05 -427.95,1103.98 -433,1098.93 -433,950.64 -395,912.64 -395,702.19 -375.62,682.81 -375.62,573.63 -272.71,470.72 v1(-266.72,470.72) ; U3.18@14.57,450 v1(14.57,510) ; v1(254,2524) 254,2369 430,2193 v1(430,2122.51) ; JP7.28@1300,100 1300,246 1343,289 1343,360 1364.57,381.57 U5.18@1364.57,450 1364.57,478.43 v1(1335,508)
A8: JP7.31 U2.71 U3.19 U5.19 U6.18 | length 8424.1
  Top Layer w10: v1(-342.62,589.7) -312.92,560 -133,560 v1(-116.44,543.44) ; v1(13.33,267.74) 332.26,267.74 354,246 573.46,246 596.05,268.58 848.25,268.58 862.83,254 890.42,254 892.42,252 998,252 1006.61,243.39 1247,243.39 v1(1267,223.39) 1283.61,240 v1(1354.5,240) ; U2.71@485.2,2057.99 485.2,2115.8 441.5,2159.5 441.5,2260.5 482,2301 530,2301 599,2370 631.46,2370 650.46,2389 1257.54,2389 1268.54,2400 1843.38,2400 2004,2239.38 v1(2004,2218) ; JP7.31@1500,0 1454,46 1370,46 1354,30 1354,-32 1390,-68 v1(2071,-68)
  Bottom Layer w10: U6.18@-408.27,1172.05 -408.27,1080.93 -415,1074.2 -415,965.16 -377,927.16 -377,724.23 -342.62,689.85 v1(-342.62,589.7) ; v1(-116.44,543.44) -96.44,523.44 -56.44,523.44 -16.93,483.93 U3.19@-16.93,450 -16.93,298 v1(13.33,267.74) ; v1(1267,223.39) 1267,243.39 1321.7,298.1 1321.7,380.24 1333.07,391.61 U5.19@1333.07,450 ; v1(1354.5,240) 1354.5,70 1370,54.5 1445.5,54.5 JP7.31@1500,0 ; v1(2004,2218) 2094,2128 2094,-45 v1(2071,-68)
A9: JP7.30 U2.66 U3.20 U5.20 U6.8 | length 5510.2
  Top Layer w10: v1(-116,307) -116,362.44 -100,378.44 70,378.44 124.44,324 433,324 453,304 522.65,304 541.23,322.58 929.83,322.58 946.42,306 1150,306 1181,337 1231,337 1257,363 1286,363 1309.34,363 ; v1(546,1708) 580,1674 750,1674 893,1531 v1(990,1531) ; v1(574.62,1995) 583.62,2004 U2.66@583.62,2057.99 ; v1(1286,339.66) 1309.34,363 ; v1(1400,223) 1424,247 1464,247 1490,273 1490,333 1460,363 1309.34,363
  Bottom Layer w10: U6.8@-211.42,1172.05 -211.42,1132.87 -252,1092.29 -252,915.43 -215.26,878.68 -215.26,710.32 -250,675.57 -250,598.71 -195,543.71 -195,439.44 -151.28,395.72 -151.28,342.28 v1(-116,307) -60,307 -48,319 -48,426.58 -48.42,427 U3.20@-48.42,450 ; v1(546,1708) 546,1966.38 v1(574.62,1995) ; v1(990,1531) 1010,1531 1177,1364 1177,1051 1127,1001 1127,946 1150,923 1150,844.5 1179,815.5 1179,702 1202,679 1202,639.32 1301.58,539.74 U5.20@1301.58,450 1301.58,355.23 v1(1286,339.66) ; JP7.30@1400,100 v1(1400,223)
A10: JP7.33 U2.65 U3.21 U5.21 U6.7 | length 7493.9
  Top Layer w10: v1(-81,341) -78,344 64.74,344 102.74,306 400.85,306 424.85,282 536.05,282 558.63,304.58 898.83,304.58 909.23,294.18 922.23,294.18 928.42,288 1188,288 1196.94,296.94 v1(1253,296.94) 1416.94,296.94 v1(1418,298) ; U2.65@603.31,2057.99 603.31,2104.31 610,2111 610,2286 695,2371 1278,2371 1282,2375 1813,2375 v1(1930,2258) ; JP7.33@1600,0 1650,50 1650,126 1670,146 v1(2052,146)
  Bottom Layer w10: U6.7@-191.73,1172.05 -191.73,1124.92 -234,1082.65 -234,937.18 -197.26,900.44 -197.26,644.74 -220,622 -220,598 -177,555 -177,482.1 -133.28,438.37 -133.28,396.28 -81,344 v1(-81,341) -79.92,342.08 U3.21@-79.92,450 ; v1(1253,296.94) 1253,372.66 1270.08,389.74 U5.21@1270.08,450 ; v1(1418,298) 1554,162 1554,71 1564,61 1564,36 JP7.33@1600,0 ; v1(1930,2258) 1970,2218 1970,2003.54 2074,1899.54 2074,168 v1(2052,146)
A11: U2.64 U3.22 U5.22 U6.6 | length 4327.2
  Top Layer w10: v1(-310,1572) -102,1572 -57,1527 v1(163,1527) ; v1(-179,613) -162,596 241,596 269,624 761,624 790,595 842,595 880,633 1073,633 1098,658 v1(1163,658) ; v1(474,1975) 489,1960 589,1960 622.99,1993.99 U2.64@622.99,2057.99
  Bottom Layer w10: v1(-310,1572) -316,1566 -316,1427.3 -269.65,1380.95 -269.65,1334.61 -172.05,1237 U6.6@-172.05,1172.05 -172.05,1102.95 -216,1059 -216,951.68 -179,914.68 v1(-179,613) -150,584 -150,491 -129.44,470.44 -111.42,470.44 U3.22@-111.42,450 ; v1(163,1527) 203,1567 203,1928 250,1975 v1(474,1975) ; v1(1163,658) 1163,637.55 1238.58,561.97 U5.22@1238.58,450
A12: U2.63 U3.23 U5.23 U6.5 | length 6818.5
  Top Layer w10: v1(434,516) 459,541 664,541 682,523 841.46,523 862.46,502 1196,502 1277,583 1446,583 v1(1472,609) ; 628,2113 628,2276.54 704.46,2353 1285.59,2353 1289.59,2357 1790,2357 1897,2250 1897,2242 v1(1937,2202) ; v1(1487,708) 1533,662 1667,662 ; 1667,662 2030,662 v1(2038,654) 1675,654 1667,662
  Bottom Layer w10: U6.5@-152.36,1172.05 -152.36,1032.41 -111.42,991.47 U3.23@-111.42,887.01 -111.42,794.66 -122.08,784 -122.08,718 -87.08,683 -12.95,683 72.05,598 212,598 294,516 v1(434,516) ; U5.23@1238.58,887.01 1238.58,855.42 1360,734 1360,701 1373,688 1467,688 v1(1487,708) 1487,624 v1(1472,609) ; v1(1937,2202) 1937,2010 2038,1909 v1(2038,654)
A13: U2.62 U3.24 U5.24 U6.4 | length 3496.8
  Top Layer w10: v1(-79.92,751) 166,751 213.82,703.18 664.68,703.18 717.5,756 911.57,756 992.57,837 1112,837 1160,885 v1(1160,981) 1180,961 v1(1233,961) ; v1(654,1707) 743.67,1707 875.67,1575 1003,1575 v1(1005.18,1577.18) ; v1(654,1897) 662.36,1905.36 U2.62@662.36,2057.99
  Bottom Layer w10: U6.4@-132.68,1172.05 -132.68,1048.73 -91,1007.05 -91,935.08 -79.92,924 U3.24@-79.92,887.01 v1(-79.92,751) ; v1(654,1707) v1(654,1897) ; v1(1005.18,1577.18) 1197,1385.36 1197,1018 v1(1160,981) ; v1(1233,961) 1270.08,923.92 U5.24@1270.08,887.01
A14: U2.56 U3.25 U5.25 U6.3 | length 3567.5
  Top Layer w10: v1(-2.6,716) 166,716 197,685 671.96,685 724.96,738 943,738 1004,799 v1(1024,799) 1044,819 1176,819 v1(1321,964) ; v1(740,1882) 780.47,1922.47 U2.56@780.47,2057.99
  Bottom Layer w10: U6.3@-112.99,1172.05 -112.99,1066.05 -73,1026.06 -73,943 -48.42,918.42 U3.25@-48.42,887.01 -48.42,761.82 v1(-2.6,716) ; v1(740,1882) 723,1865 723,1437 716,1430 716,1378 730,1364 920,1364 927,1357 927,1105 978.84,1053.16 978.84,1026 1029,975.84 1029,824 1024,819 v1(1024,799) ; U5.25@1301.58,887.01 1301.58,944.58 v1(1321,964)
A15: U2.55 U3.26 U5.26 U6.2 | length 5387.7
  Top Layer w10: v1(352,589) 358,595 699,595 717,577 867,577 905,615 1094,615 1104,625 1178,625 1196,643 1315,643 v1(1393,721) ; U2.55@800.16,2057.99 800.16,2110 807,2116.84 v1(807,2231) ; v1(807,2300) 832,2325 1314,2325 1328,2339 1754,2339 v1(1769,2324) ; v1(1360,829) 1461,930 1681,930 v1(1811,1060)
  Bottom Layer w10: U6.2@-93.31,1172.05 -93.31,1074.89 -55,1036.59 -55,970 -16.93,931.93 U3.26@-16.93,887.01 -16.93,800.93 150,634 248,634 293,589 v1(352,589) ; v1(807,2231) v1(807,2300) ; U5.26@1333.07,887.01 1333.07,855.93 v1(1360,829) 1360,785 1393,752 v1(1393,721) ; v1(1769,2324) 1716,2271 1716,1708 1639,1631 1639,1330 1744.5,1224.5 1800.5,1224.5 1815,1210 1815,1174 1780,1139 1780,1091 v1(1811,1060)
A16: U2.53 U3.27 U5.27 U6.1 | length 4659.3
  Top Layer w10: v1(164,667) 714.5,667 753.5,706 940.52,706 986.28,751.75 1027.14,751.75 1076.38,801 1211,801 v1@1357.28,947.28 ; U2.53@839.53,2057.99 840,2218.47 840,2239 890,2289 1289,2289 1329,2249 1486,2249 1501,2234 1592,2234 v1(1657,2169) ; v1(1364.57,940) 1468.57,1044 v1(1735,1044)
  Bottom Layer w10: U6.1@-73.62,1172.05 -73.62,1085.22 -30,1041.6 -30,978 14.57,933.43 U3.27@14.57,887.01 14.57,816.43 v1(164,667) ; U5.27@1364.57,887.01 v1(1364.57,940) ; v1(1657,2169) 1686.46,2139.54 1686.46,1793.46 1621,1728 1621,1291 1735,1177 v1(1735,1044)
A17: U2.48 U3.42 U5.42 U6.48 | length 4479.1
  Top Layer w10: v1(-51,1581) v1(-51,1706) ; v1(373,1136) 424,1085 v1(461,1085) ; v1(546,778) 560.01,792 780,792 796,808 796,832 821.26,857.26 910.93,857.26 962.67,909 1046.98,909 1091,953.02 1091,1060.5 v1(1106,1075.5) 1124.53,1094.03 1247,1094.03 1253.97,1101 1678.67,1101 1769.17,1191.5 v1(1782,1191.5) ; U2.48@937.95,2057.99 937.95,1954.24 v1(987.95,1904.24)
  Bottom Layer w10: U6.48@-73.62,1927.95 -73.62,1903 -74,1902.62 -74,1729 v1(-51,1706) ; v1(-51,1581) -51,1560 v1(373,1136) ; v1(461,1085) 487.01,1058.99 U3.42@487.01,887.01 487.01,836.99 v1(546,778) ; v1(987.95,1904.24) 987.95,1754.95 862,1629 862,1503 930.16,1434.84 951.38,1434.84 981,1405.23 981,1380 1013,1348 1057.68,1348 1139,1266.68 1139,1108.5 v1(1106,1075.5) ; v1(1782,1191.5) 1762,1171.5 1762,1083 1778,1067 1778,1007.65 1837.01,948.64 U5.42@1837.01,887.01
A18: U2.47 U3.43 U5.43 U6.17 | length 4682.4
  Top Layer w10: v1(-342,790) -332,780 -106,780 -99.25,786.75 195.14,786.75 260.72,721.18 626.18,721.18 v1(656,751) 679,774 893,774 992,873 1122,873 1127,878 1127,1001 1169,1043 v1(1233,1043) 1276,1043 1298,1065 1707,1065 1735.79,1093.79 1789.79,1093.79 v1(1813,1117) ; U2.47@957.64,2057.99 957.64,1990 1021,1926.64 1021,1882 995,1856 858,1856 832,1830 832,1796 987,1641 v1(1012,1641)
  Bottom Layer w10: U6.17@-388.58,1172.05 -388.58,1071.42 -397,1063 -397,1006.5 -359,968.5 -359,807 v1(-342,790) ; U3.43@518.5,887.01 518.5,850 540.5,828 579,828 v1(656,751) ; v1(1012,1641) 1123,1530 1123,1490 1217,1396 1217,1059 v1(1233,1043) ; v1(1813,1117) 1868.5,1061.5 U5.43@1868.5,887.01
A19: U2.46 U3.44 U5.44 U6.16 | length 5202.8
  Top Layer w10: v1(-364,1030) -434,1030 -474,990 -474,890 -461,877 -303.12,877 -298.17,872.05 -46.7,872.05 -31.48,887.28 260.28,887.28 290,917 v1@585,917 ; v1(832,813) 906.47,813 984.47,891 1090,891 1109,910 1109,1015.04 1169.99,1076.03 1265,1076.03 1271.97,1083 1691,1083 1722.4,1114.4 1753.57,1114.4 v1(1855,1215.82) ; U2.46@977.32,2057.99 977.32,2003.68 990,1991 1262,1991 1271,2000 1498,2000 1557.41,1940.59 1670.41,1940.59 v1(1794,1817)
  Bottom Layer w10: U6.16@-368.9,1172.05 -368.9,1034.9 v1(-364,1030) ; U3.44@550,887.01 U3.44@550,888 ; v1@585,917 550,917 U3.44@550,888 ; v1(832,813) 757,888 U3.44@550,888 ; v1(1794,1817) 1794,1727 1657,1590 1657,1352.19 1682.19,1327 1768,1327 1855,1240 ; v1(1855,1215.82) 1855,1240 ; U5.44@1900,887.01 1900,1195 1867.09,1227.91 1855,1240
  other v1: 575,925
A20: U2.45 U6.9 | length 3745.1
  Top Layer w10: v1(-310,1346) -366,1346 -485,1465 -485,1704 -465,1724 -465,1895.46 -375,1985.46 -375,2133 -307,2201 -307,2341 -245,2403 v1(-245,2727) ; v1(917,2198) 997.01,2117.99 U2.45@997.01,2057.99
  Bottom Layer w10: v1(-310,1346) -231.1,1267.1 U6.9@-231.1,1172.05 ; v1(-245,2727) -90,2882 694,2882 746,2830 746,2681 801.5,2625.5 801.5,2400.5 917,2285 v1(917,2198)
A21: U2.44 U6.10 | length 2828.9
  Top Layer w10: v1(-310,1621) -284,1621 -145,1760 v1(-41,1760) ; v1(-41,2075) -41,2136 71,2248 138,2248 290,2400 381.39,2400 481.39,2500 515.5,2500 533,2482.5 815.5,2482.5 v1(853,2520) ; v1(988,2178) 1016.69,2149.31 U2.44@1016.69,2057.99
  Bottom Layer w10: v1(-310,1621) -343,1588 -343,1322 -250.79,1229.79 U6.10@-250.79,1172.05 ; v1(-41,1760) -41,1952 -7,1986 -7,2041 v1(-41,2075) ; v1(853,2520) 863,2510 863,2391.46 968,2286.46 968,2198 v1(988,2178)
D0: JP7.7 U2.98 U3.7 U6.29 | length 7260.6
  Top Layer w10: v1(-691,51) v1(-568,-72) ; v1(-289,115) -258.5,145.5 25.5,145.5 50,121 50,77 76.69,50.31 249.69,50.31 JP7.7@300,0 ; v1(77,1616) 77,1672 58,1691 3,1691 -8,1680 -8,1590 22,1560 182.63,1560 230.63,1512 286,1512 325.64,1472.36 U2.98@372.01,1472.36
  Bottom Layer w10: v1(-691,51) -729,89 -729,417 -787,475 -787,908 -777,918 -777,1214.09 -763,1228.09 -763,1435 -702,1496 -702,1777 -675,1804 -471,1804 -459,1816 -459,1871.64 -447.64,1883 U6.29@-447.64,1927.95 -447.64,1978.64 -502.17,2033.17 -502.17,2287.17 -535.64,2320.64 -535.64,2383.64 -537,2385 -672,2385 -701,2356 -750,2356 -808,2414 -808,2527 -801,2534 -286.02,2534 29,2218.98 29,1950 11,1932 11,1810 77,1744 v1(77,1616) ; v1(-568,-72) -351,-72 -289,-10 v1(-289,115) ; JP7.7@300,0 331,0 331,13.5 363.5,46 422,46 446,70 446,271.53 361,356.53 361,428.98 U3.7@361.02,450
D1: JP7.6 U2.105 U3.8 U6.31 | length 4565.3
  Top Layer w10: v1(-505,252) -374,252 -285.5,163.5 136.5,163.5 JP7.6@200,100 ; v1(-503,1771) -503,1448.76 -367,1312.76 -290,1312.76 -253.76,1349 150,1349 193,1306 250,1306 278.57,1334.57 U2.105@372.01,1334.57
  Bottom Layer w10: v1(-505,252) -505,303 -550,348 -623,348 -665,390 -665,712 -701,748 -701,840 -683,858 -683,1134 -659,1158 -659,1307 -618,1348 -618,1410 -567,1461 -567,1577 -570,1580 -570,1704 v1(-503,1771) -474,1771 -435,1810 -435,1863 -408.27,1889.73 U6.31@-408.27,1927.95 ; JP7.6@200,100 236.5,63.5 263.5,63.5 273,54 330,54 346,70 346,322.06 329.53,338.53 U3.8@329.53,450
D2: JP7.9 U2.106 U3.9 U6.33 | length 4357.3
  Top Layer w10: v1(-543,386) -515,358 -339.35,358 -265.67,284.33 -265.67,258.67 -214,207 164,207 204,167 v1(306,167) 346,127 346,54 JP7.9@400,0 ; v1(-536.5,1609) -521,1593.5 -521,1422 -393.76,1294.76 -259,1294.76 -222.76,1331 114,1331 158,1287 273.27,1287 301.16,1314.88 U2.106@372.01,1314.88
  Bottom Layer w10: v1(-543,386) -647,490 -647,658 -626,679 -626,868.42 -604,890.42 -604,1036 -613,1045 -613,1092 -603,1102 -603,1195 -584,1214 -584,1374.43 -544.97,1413.47 -544.97,1600.53 v1(-536.5,1609) -536.5,1682.51 -489.4,1729.61 -457.46,1729.61 -368.9,1818.17 U6.33@-368.9,1927.95 ; U3.9@298.03,450 298.03,174.97 v1(306,167)
D3: JP7.8 U2.108 U3.10 U6.35 | length 4163.5
  Top Layer w10: v1(-300,250) -231.5,181.5 153.5,181.5 189,146 254,146 JP7.8@300,100 ; v1(-136,1232) -136,1228 -131,1223 317,1223 341,1247 341,1275.51 U2.108@372.01,1275.51
  Bottom Layer w10: U6.35@-329.53,1927.95 -329.53,1770.53 -289,1730 ; v1(-300,250) -340,290 -340,336 -608,604 -608,821 -581,848 -581,1024 -547,1058 -547,1315 -467,1395 -467,1670 -451,1686 -397.53,1686 -353.53,1730 -289,1730 ; v1(-136,1232) -250,1346 -250,1691 -289,1730 ; U3.10@266.54,450 266.54,294.09 273,287.62 273,127 JP7.8@300,100
D4: JP7.11 U2.109 U3.13 U6.38 | length 5613.2
  Top Layer w10: v1(-730,1229) -697,1196 -380,1196 -303,1119 136,1119 v1(155,1138) 204,1187 465.51,1187 U2.109@465.51,1182.01 ; v1(-468,115) -468,90 -425,47 44.5,47 46,45.5 46,-22 70,-46 454,-46 JP7.11@500,0
  Bottom Layer w10: v1(-730,1229) -755.23,1203.77 -755.23,909 -764,900.23 -764,603 -686,525 -686,171 -665,150 -503,150 v1(-468,115) ; U6.38@-270.47,1927.95 -270.47,1775.47 -203,1708 -203,1541.78 -10.48,1349.26 -10.48,1303.48 v1(155,1138) ; U3.13@172.05,450 172.05,334.95 255,252 255,196.74 240,181.74 205.74,181.74 154,130 154,70.25 178.75,45.5 230.5,45.5 246,30 246,-22 269.5,-45.5 454.5,-45.5 JP7.11@500,0
D5: JP7.10 U2.114 U3.14 U6.40 | length 7684.3
  Top Layer w10: v1(-775,2501) -990,2501 -1051,2440 -1051,213 -990,152 -730,152 -605,27 -149,27 -53,-69 510,-69 546,-33 546,137 v1(555,146) 446,146 JP7.10@400,100 400,136 321,215 v1(222,215) ; v1(-231.1,2039) -175,2095.1 v1(-175,2293) ; v1(540,1100) 563.94,1123.94 U2.114@563.94,1182.01 ; v1(589,488) v1(812,488)
  Bottom Layer w10: v1(-775,2501) -383,2501 v1(-175,2293) ; U6.40@-231.1,1927.95 v1(-231.1,2039) ; U3.14@140.55,450 140.55,296.45 v1(222,215) ; v1(540,1100) 610.09,1100 865,845.09 865,779 844,758 844,520 v1(812,488) ; v1(555,146) 583,174 583,482 v1(589,488)
D6: JP7.13 U2.115 U3.15 U6.42 | length 6631.4
  Top Layer w10: v1(-814,1272) -814,1222 -750,1158 -410.41,1158 -198.46,946.05 -142.62,946.05 -32.17,1056.5 289.5,1056.5 324,1091 383.75,1091 427.75,1047 540,1047 583.62,1090.62 U2.115@583.62,1182.01 ; v1(-689.23,2088.77) -612,2166 v1(-405.1,2166) ; v1(-325,80) -70,80 v1(-60,90)
  Bottom Layer w10: v1(-689.23,2088.77) -786,1992 -786,1479 -814,1451 v1(-814,1272) -814,992 -848,958 -848,294 -780,226 -780,33.67 -724.33,-22 -427,-22 v1(-325,80) ; v1(-405.1,2166) -351.85,2112.75 -254.48,2112.75 -191.73,2050 U6.42@-191.73,1927.95 ; v1(-60,90) -60,110 -17,153 31,153 54,130 ; U3.15@109.06,450 109.06,212.06 54,157 54,130 ; JP7.13@600,0 536,-64 170,-64 146,-40 146,42 134,54 64,54 54,64 54,130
